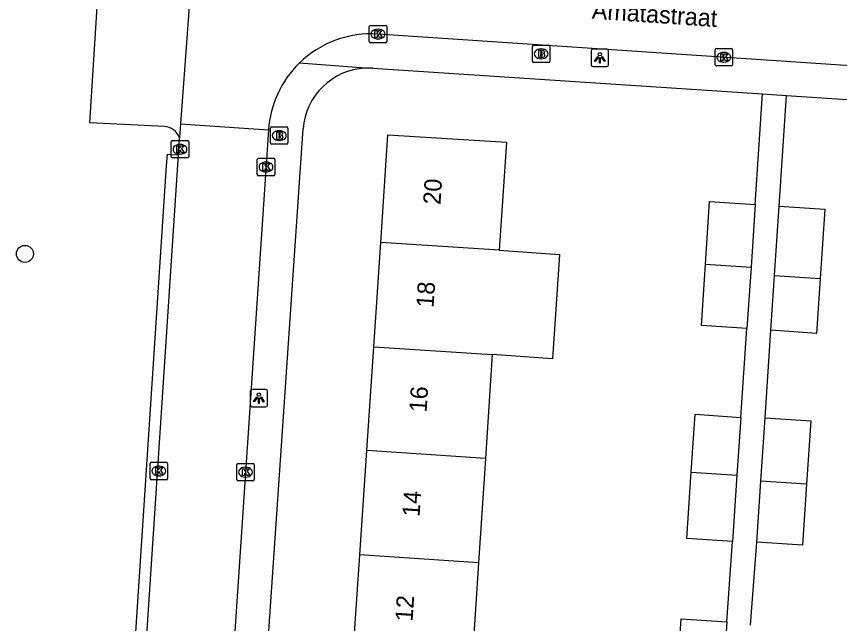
# Model space of a CAD drawing. Extents: x 161848 to 162726, y 385382 to 386521.
# Drawn here: x 161939.2 to 161986.5, y 385809.54 to 385844.42 of the extents above; entities that cross this region are included whole.
import ezdxf

# ---------------------------------------------------------------- set-up
doc = ezdxf.new("R2010")
doc.units = 0
for name, color, linetype in [('IMGEO_Boom', 7, 'Continuous'), ('IMGEO_Brandkraan', 7, 'Continuous'), ('IMGEO_Kolk', 7, 'Continuous'), ('IMGEO_Lichtpunt', 7, 'Continuous'), ('IMGEO_Openbare_ruimte_label', 7, 'Continuous'), ('IMGEO_Pand', 7, 'Continuous'), ('IMGEO_Pand_nummerreeks', 7, 'Continuous'), ('IMGEO_Parkeervlak_open', 7, 'Continuous'), ('IMGEO_Rijbaan_lokaal_open', 7, 'Continuous'), ('IMGEO_Verkeerseiland_open', 7, 'Continuous'), ('IMGEO_Voetpad_open', 7, 'Continuous')]:
    doc.layers.add(name, color=color, linetype=linetype)

msp = doc.modelspace()

# ---------------------------------------------------------------- linework, layer by layer
at = {"layer": 'IMGEO_Boom'}
msp.add_circle((161939.691, 385830.779), 0.489, dxfattribs=at)
at = {"layer": 'IMGEO_Brandkraan'}
for p, q in [((161968.848, 385841.847), (161968.848, 385842.699)), ((161968.923, 385842.773), (161969.775, 385842.773)), ((161969.336, 385842.553), (161969.361, 385842.553)), ((161969.849, 385842.699), (161969.849, 385841.847)), ((161969.359, 385841.993), (161969.334, 385841.993)), ((161969.775, 385841.773), (161968.923, 385841.773)), ((161953.803, 385837.151), (161953.803, 385838.003)), ((161953.878, 385838.077), (161954.73, 385838.077)), ((161954.291, 385837.857), (161954.316, 385837.857)), ((161954.804, 385838.003), (161954.804, 385837.151)), ((161954.314, 385837.297), (161954.289, 385837.297)), ((161954.73, 385837.077), (161953.878, 385837.077))]:
    msp.add_line(p, q, dxfattribs=at)
for points in [[(161968.848, 385841.847), (161968.848, 385842.699)], [(161968.923, 385842.773), (161969.775, 385842.773)], [(161969.196, 385842.473), (161969.196, 385842.073), (161969.409, 385842.073)], [(161969.427, 385842.473), (161969.196, 385842.473)], [(161969.375, 385842.392), (161969.321, 385842.392), (161969.321, 385842.316)], [(161969.849, 385842.699), (161969.849, 385841.847)], [(161969.321, 385842.316), (161969.374, 385842.316)], [(161969.383, 385842.24), (161969.321, 385842.24), (161969.321, 385842.159)], [(161969.321, 385842.159), (161969.383, 385842.159)], [(161969.775, 385841.773), (161968.923, 385841.773)], [(161953.803, 385837.151), (161953.803, 385838.003)], [(161953.878, 385838.077), (161954.73, 385838.077)], [(161954.151, 385837.777), (161954.151, 385837.377), (161954.364, 385837.377)], [(161954.382, 385837.777), (161954.151, 385837.777)], [(161954.33, 385837.696), (161954.276, 385837.696), (161954.276, 385837.62)], [(161954.804, 385838.003), (161954.804, 385837.151)], [(161954.276, 385837.62), (161954.329, 385837.62)], [(161954.338, 385837.544), (161954.276, 385837.544), (161954.276, 385837.463)], [(161954.276, 385837.463), (161954.338, 385837.463)], [(161954.73, 385837.077), (161953.878, 385837.077)]]:
    msp.add_lwpolyline(points, dxfattribs=at)
for centre, radius, start, end in [((161968.925, 385842.697), 0.0765, 91.552, 178.448), ((161968.925, 385842.697), 0.0765, 91.552, 178.448), ((161969.376, 385842.354), 0.0379, 267.8285, 90.9355), ((161969.431, 385842.328), 0.145, 59.4692, 91.5367), ((161969.456, 385842.375), 0.0922, 285.5137, 58.1501), ((161969.773, 385842.697), 0.0765, 1.552, 88.448), ((161969.773, 385842.697), 0.0765, 1.552, 88.448), ((161969.384, 385842.199), 0.0404, 269.8759, 90.5077), ((161969.415, 385842.324), 0.251, 268.6676, 293.5347), ((161969.461, 385842.183), 0.105, 301.3115, 78.989), ((161968.925, 385841.849), 0.0765, 181.552, 268.448), ((161968.925, 385841.849), 0.0765, 181.552, 268.448), ((161969.773, 385841.849), 0.0765, 271.552, 358.448), ((161969.773, 385841.849), 0.0765, 271.552, 358.448), ((161953.88, 385838.001), 0.0765, 91.552, 178.448), ((161953.88, 385838.001), 0.0765, 91.552, 178.448), ((161954.331, 385837.658), 0.0379, 267.8285, 90.9355), ((161954.386, 385837.632), 0.145, 59.4692, 91.5367), ((161954.411, 385837.679), 0.0922, 285.5137, 58.1501), ((161954.728, 385838.001), 0.0765, 1.552, 88.448), ((161954.728, 385838.001), 0.0765, 1.552, 88.448), ((161953.88, 385837.153), 0.0765, 181.552, 268.448), ((161953.88, 385837.153), 0.0765, 181.552, 268.448), ((161954.339, 385837.503), 0.0404, 269.8759, 90.5077), ((161954.37, 385837.628), 0.251, 268.6676, 293.5347), ((161954.416, 385837.487), 0.105, 301.3115, 78.989), ((161954.728, 385837.153), 0.0765, 271.552, 358.448), ((161954.728, 385837.153), 0.0765, 271.552, 358.448)]:
    msp.add_arc(centre, radius, start, end, dxfattribs=at)
for centre, major_axis, ratio, start_param, end_param in [((161969.335, 385842.273), (-0.387, 0.002), 0.722429, 4.712389, 7.853982), ((161969.36, 385842.273), (-0.39, 0.002), 0.717154, 1.570796, 4.712389), ((161954.29, 385837.577), (-0.387, 0.002), 0.722429, 4.712389, 7.853982), ((161954.315, 385837.577), (-0.39, 0.002), 0.717154, 1.570796, 4.712389)]:
    msp.add_ellipse(centre, major_axis=major_axis, ratio=ratio, start_param=start_param, end_param=end_param, dxfattribs=at)
at = {"layer": 'IMGEO_Kolk'}
for p, q in [((161959.477, 385842.983), (161959.477, 385843.835)), ((161959.552, 385843.909), (161960.404, 385843.909)), ((161960.478, 385843.835), (161960.478, 385842.983)), ((161959.965, 385843.689), (161959.99, 385843.689)), ((161960.404, 385842.909), (161959.552, 385842.909)), ((161959.988, 385843.129), (161959.963, 385843.129)), ((161979.346, 385841.649), (161979.346, 385842.501)), ((161979.421, 385842.575), (161980.273, 385842.575)), ((161979.834, 385842.355), (161979.859, 385842.355)), ((161980.347, 385842.501), (161980.347, 385841.649)), ((161980.273, 385841.575), (161979.421, 385841.575)), ((161979.857, 385841.795), (161979.832, 385841.795)), ((161948.098, 385836.363), (161948.098, 385837.215)), ((161948.173, 385837.289), (161949.025, 385837.289)), ((161949.099, 385837.215), (161949.099, 385836.363)), ((161948.586, 385837.069), (161948.611, 385837.069)), ((161949.025, 385836.289), (161948.173, 385836.289)), ((161948.609, 385836.509), (161948.584, 385836.509)), ((161953.116, 385836.269), (161953.968, 385836.269)), ((161953.041, 385835.343), (161953.041, 385836.195)), ((161953.529, 385836.049), (161953.554, 385836.049)), ((161954.042, 385836.195), (161954.042, 385835.343)), ((161953.968, 385835.269), (161953.116, 385835.269)), ((161953.552, 385835.489), (161953.527, 385835.489)), ((161946.886, 385817.876), (161946.886, 385818.728)), ((161946.961, 385818.802), (161947.813, 385818.802)), ((161947.887, 385818.728), (161947.887, 385817.876)), ((161951.937, 385818.737), (161952.789, 385818.737)), ((161947.374, 385818.582), (161947.399, 385818.582)), ((161951.862, 385817.811), (161951.862, 385818.663)), ((161952.35, 385818.517), (161952.375, 385818.517)), ((161952.863, 385818.663), (161952.863, 385817.811)), ((161947.813, 385817.802), (161946.961, 385817.802)), ((161947.397, 385818.022), (161947.372, 385818.022)), ((161952.373, 385817.957), (161952.348, 385817.957)), ((161952.789, 385817.737), (161951.937, 385817.737))]:
    msp.add_line(p, q, dxfattribs=at)
for points in [[(161959.477, 385842.983), (161959.477, 385843.835)], [(161959.552, 385843.909), (161960.404, 385843.909)], [(161960.478, 385843.835), (161960.478, 385842.983)], [(161959.798, 385843.609), (161959.921, 385843.609), (161959.921, 385843.458), (161960.051, 385843.609), (161960.215, 385843.609), (161960.069, 385843.458), (161960.222, 385843.209), (161960.07, 385843.209), (161959.985, 385843.373), (161959.921, 385843.306), (161959.921, 385843.209), (161959.798, 385843.209), (161959.798, 385843.609)], [(161960.404, 385842.909), (161959.552, 385842.909)], [(161979.346, 385841.649), (161979.346, 385842.501)], [(161979.421, 385842.575), (161980.273, 385842.575)], [(161980.347, 385842.501), (161980.347, 385841.649)], [(161979.667, 385842.275), (161979.79, 385842.275), (161979.79, 385842.124), (161979.92, 385842.275), (161980.084, 385842.275), (161979.938, 385842.124), (161980.091, 385841.875), (161979.939, 385841.875), (161979.854, 385842.039), (161979.79, 385841.972), (161979.79, 385841.875), (161979.667, 385841.875), (161979.667, 385842.275)], [(161980.273, 385841.575), (161979.421, 385841.575)], [(161948.098, 385836.363), (161948.098, 385837.215)], [(161948.173, 385837.289), (161949.025, 385837.289)], [(161949.099, 385837.215), (161949.099, 385836.363)], [(161948.419, 385836.989), (161948.542, 385836.989), (161948.542, 385836.838), (161948.672, 385836.989), (161948.836, 385836.989), (161948.69, 385836.838), (161948.843, 385836.589), (161948.691, 385836.589), (161948.606, 385836.753), (161948.542, 385836.686), (161948.542, 385836.589), (161948.419, 385836.589), (161948.419, 385836.989)], [(161949.025, 385836.289), (161948.173, 385836.289)], [(161953.116, 385836.269), (161953.968, 385836.269)], [(161953.041, 385835.343), (161953.041, 385836.195)], [(161953.362, 385835.969), (161953.485, 385835.969), (161953.485, 385835.818), (161953.615, 385835.969), (161953.779, 385835.969), (161953.633, 385835.818), (161953.786, 385835.569), (161953.634, 385835.569), (161953.549, 385835.733), (161953.485, 385835.666), (161953.485, 385835.569), (161953.362, 385835.569), (161953.362, 385835.969)], [(161954.042, 385836.195), (161954.042, 385835.343)], [(161953.968, 385835.269), (161953.116, 385835.269)], [(161946.886, 385817.876), (161946.886, 385818.728)], [(161946.961, 385818.802), (161947.813, 385818.802)], [(161947.887, 385818.728), (161947.887, 385817.876)], [(161951.937, 385818.737), (161952.789, 385818.737)], [(161947.207, 385818.502), (161947.33, 385818.502), (161947.33, 385818.351), (161947.46, 385818.502), (161947.624, 385818.502), (161947.478, 385818.351), (161947.631, 385818.102), (161947.479, 385818.102), (161947.394, 385818.266), (161947.33, 385818.199), (161947.33, 385818.102), (161947.207, 385818.102), (161947.207, 385818.502)], [(161951.862, 385817.811), (161951.862, 385818.663)], [(161952.183, 385818.437), (161952.306, 385818.437), (161952.306, 385818.286), (161952.436, 385818.437), (161952.6, 385818.437), (161952.454, 385818.286), (161952.607, 385818.037), (161952.455, 385818.037), (161952.37, 385818.201), (161952.306, 385818.134), (161952.306, 385818.037), (161952.183, 385818.037), (161952.183, 385818.437)], [(161952.863, 385818.663), (161952.863, 385817.811)], [(161947.813, 385817.802), (161946.961, 385817.802)], [(161952.789, 385817.737), (161951.937, 385817.737)]]:
    msp.add_lwpolyline(points, dxfattribs=at)
for centre, start, end in [((161959.554, 385843.833), 91.552, 178.448), ((161959.554, 385843.833), 91.552, 178.448), ((161960.402, 385843.833), 1.552, 88.448), ((161960.402, 385843.833), 1.552, 88.448), ((161959.554, 385842.985), 181.552, 268.448), ((161959.554, 385842.985), 181.552, 268.448), ((161960.402, 385842.985), 271.552, 358.448), ((161960.402, 385842.985), 271.552, 358.448), ((161979.423, 385842.499), 91.552, 178.448), ((161979.423, 385842.499), 91.552, 178.448), ((161980.271, 385842.499), 1.552, 88.448), ((161980.271, 385842.499), 1.552, 88.448), ((161979.423, 385841.651), 181.552, 268.448), ((161979.423, 385841.651), 181.552, 268.448), ((161980.271, 385841.651), 271.552, 358.448), ((161980.271, 385841.651), 271.552, 358.448), ((161948.175, 385837.213), 91.552, 178.448), ((161948.175, 385837.213), 91.552, 178.448), ((161949.023, 385837.213), 1.552, 88.448), ((161949.023, 385837.213), 1.552, 88.448), ((161948.175, 385836.365), 181.552, 268.448), ((161948.175, 385836.365), 181.552, 268.448), ((161949.023, 385836.365), 271.552, 358.448), ((161949.023, 385836.365), 271.552, 358.448), ((161953.118, 385836.193), 91.552, 178.448), ((161953.118, 385836.193), 91.552, 178.448), ((161953.966, 385836.193), 1.552, 88.448), ((161953.966, 385836.193), 1.552, 88.448), ((161953.118, 385835.345), 181.552, 268.448), ((161953.118, 385835.345), 181.552, 268.448), ((161953.966, 385835.345), 271.552, 358.448), ((161953.966, 385835.345), 271.552, 358.448), ((161946.963, 385818.726), 91.552, 178.448), ((161946.963, 385818.726), 91.552, 178.448), ((161947.811, 385818.726), 1.552, 88.448), ((161947.811, 385818.726), 1.552, 88.448), ((161951.939, 385818.661), 91.552, 178.448), ((161951.939, 385818.661), 91.552, 178.448), ((161952.787, 385818.661), 1.552, 88.448), ((161952.787, 385818.661), 1.552, 88.448), ((161946.963, 385817.878), 181.552, 268.448), ((161946.963, 385817.878), 181.552, 268.448), ((161947.811, 385817.878), 271.552, 358.448), ((161947.811, 385817.878), 271.552, 358.448), ((161951.939, 385817.813), 181.552, 268.448), ((161951.939, 385817.813), 181.552, 268.448), ((161952.787, 385817.813), 271.552, 358.448), ((161952.787, 385817.813), 271.552, 358.448)]:
    msp.add_arc(centre, 0.0765, start, end, dxfattribs=at)
for centre, major_axis, ratio, start_param, end_param in [((161959.964, 385843.409), (-0.387, 0.002), 0.722429, 4.712389, 7.853982), ((161959.989, 385843.409), (-0.39, 0.002), 0.717154, 1.570796, 4.712389), ((161979.833, 385842.075), (-0.387, 0.002), 0.722429, 4.712389, 7.853982), ((161979.858, 385842.075), (-0.39, 0.002), 0.717154, 1.570796, 4.712389), ((161948.585, 385836.789), (-0.387, 0.002), 0.722429, 4.712389, 7.853982), ((161948.61, 385836.789), (-0.39, 0.002), 0.717154, 1.570796, 4.712389), ((161953.528, 385835.769), (-0.387, 0.002), 0.722429, 4.712389, 7.853982), ((161953.553, 385835.769), (-0.39, 0.002), 0.717154, 1.570796, 4.712389), ((161947.373, 385818.302), (-0.387, 0.002), 0.722429, 4.712389, 7.853982), ((161947.398, 385818.302), (-0.39, 0.002), 0.717154, 1.570796, 4.712389), ((161952.349, 385818.237), (-0.387, 0.002), 0.722429, 4.712389, 7.853982), ((161952.374, 385818.237), (-0.39, 0.002), 0.717154, 1.570796, 4.712389)]:
    msp.add_ellipse(centre, major_axis=major_axis, ratio=ratio, start_param=start_param, end_param=end_param, dxfattribs=at)
at = {"layer": 'IMGEO_Lichtpunt'}
for p, q in [((161972.227, 385842.451), (161972.227, 385841.644)), ((161972.227, 385842.451), (161972.227, 385841.644)), ((161973.129, 385842.546), (161972.321, 385842.546)), ((161973.129, 385842.546), (161972.321, 385842.546)), ((161973.223, 385841.644), (161973.223, 385842.451)), ((161973.223, 385841.644), (161973.223, 385842.451)), ((161972.321, 385841.55), (161973.129, 385841.55)), ((161972.321, 385841.55), (161973.129, 385841.55)), ((161953.535, 385822.99), (161952.727, 385822.99)), ((161953.535, 385822.99), (161952.727, 385822.99)), ((161952.633, 385822.895), (161952.633, 385822.088)), ((161952.633, 385822.895), (161952.633, 385822.088)), ((161953.629, 385822.088), (161953.629, 385822.895)), ((161953.629, 385822.088), (161953.629, 385822.895)), ((161952.727, 385821.994), (161953.535, 385821.994)), ((161952.727, 385821.994), (161953.535, 385821.994))]:
    msp.add_line(p, q, dxfattribs=at)
for points in [[(161972.601, 385842.115), (161972.64, 385842.087), (161972.452, 385841.825), (161972.414, 385841.852), (161972.601, 385842.115)], [(161972.703, 385842.067), (161972.75, 385842.067), (161972.75, 385841.745), (161972.703, 385841.745), (161972.703, 385842.067)], [(161972.813, 385842.087), (161972.851, 385842.114), (161973.038, 385841.852), (161972.999, 385841.824), (161972.813, 385842.087)], [(161953.007, 385822.559), (161953.046, 385822.531), (161952.858, 385822.269), (161952.82, 385822.296), (161953.007, 385822.559)], [(161953.109, 385822.511), (161953.156, 385822.511), (161953.156, 385822.189), (161953.109, 385822.189), (161953.109, 385822.511)], [(161953.219, 385822.531), (161953.257, 385822.558), (161953.444, 385822.296), (161953.405, 385822.268), (161953.219, 385822.531)]]:
    msp.add_lwpolyline(points, dxfattribs=at)
for centre in [(161972.726, 385842.249), (161953.132, 385822.693)]:
    msp.add_circle(centre, 0.0994, dxfattribs=at)
for centre, start, end in [((161972.321, 385842.451), 90, 180), ((161972.321, 385842.451), 90, 180), ((161973.129, 385842.451), 0, 90), ((161973.129, 385842.451), 0, 90), ((161972.321, 385841.644), 180, 270), ((161972.321, 385841.644), 180, 270), ((161973.129, 385841.644), 270, 0), ((161973.129, 385841.644), 270, 360), ((161952.727, 385822.895), 90, 180), ((161952.727, 385822.895), 90, 180), ((161953.535, 385822.895), 0, 90), ((161953.535, 385822.895), 0, 90), ((161952.727, 385822.088), 180, 270), ((161952.727, 385822.088), 180, 270), ((161953.535, 385822.088), 270, 0), ((161953.535, 385822.088), 270, 360)]:
    msp.add_arc(centre, 0.0946, start, end, dxfattribs=at)
at = {"layer": 'IMGEO_Pand'}
for points in [[(161960.132, 385831.44), (161960.546, 385837.627), (161967.351, 385837.188), (161966.94, 385830.984)], [(161978.792, 385830.19), (161979.031, 385833.792), (161981.653, 385833.619)], [(161981.653, 385833.619), (161981.414, 385830.015)], [(161982.767, 385829.543), (161983.031, 385833.522)], [(161983.031, 385833.522), (161985.651, 385833.348), (161985.387, 385829.37)], [(161959.731, 385825.445), (161960.132, 385831.44)], [(161966.94, 385830.984), (161960.132, 385831.44)], [(161966.94, 385830.984), (161970.408, 385830.752), (161970.006, 385824.757), (161966.543, 385824.989)], [(161981.18, 385826.49), (161978.559, 385826.664), (161978.792, 385830.19)], [(161978.792, 385830.19), (161981.414, 385830.015)], [(161981.414, 385830.015), (161981.18, 385826.49)], [(161982.558, 385826.386), (161982.767, 385829.543)], [(161985.387, 385829.37), (161985.178, 385826.212), (161982.558, 385826.386)], [(161982.767, 385829.543), (161985.387, 385829.37)], [(161959.331, 385819.481), (161959.731, 385825.445)], [(161959.731, 385825.445), (161966.543, 385824.989)], [(161966.543, 385824.989), (161966.148, 385819.025)], [(161977.978, 385818.234), (161978.199, 385821.56), (161980.821, 385821.387)], [(161980.821, 385821.387), (161980.6, 385818.058)], [(161981.979, 385817.712), (161982.22, 385821.354)], [(161982.22, 385821.354), (161984.84, 385821.18), (161984.599, 385817.539)], [(161958.93, 385813.487), (161959.331, 385819.481)], [(161966.148, 385819.025), (161959.331, 385819.481)], [(161966.148, 385819.025), (161965.751, 385813.03)], [(161980.348, 385814.258), (161977.727, 385814.432), (161977.978, 385818.234)], [(161977.978, 385818.234), (161980.6, 385818.058)], [(161980.6, 385818.058), (161980.348, 385814.258)], [(161981.747, 385814.218), (161981.979, 385817.712)], [(161984.599, 385817.539), (161984.367, 385814.044), (161981.747, 385814.218)], [(161984.599, 385817.539), (161981.979, 385817.712)], [(161958.535, 385807.578), (161958.93, 385813.487)], [(161965.751, 385813.03), (161958.93, 385813.487)], [(161965.751, 385813.03), (161965.359, 385807.121)], [(161977.162, 385806.331), (161977.392, 385809.804), (161980.014, 385809.631)], [(161980.014, 385809.631), (161979.783, 385806.155)]]:
    msp.add_lwpolyline(points, dxfattribs=at)
at = {"layer": 'IMGEO_Parkeervlak_open'}
msp.add_lwpolyline([(161947.7, 385838.093), (161943.41, 385838.314), (161943.973, 385847.108)], dxfattribs=at)
msp.add_arc((161947.651, 385837.125), 0.969, 19.1981, 87.1044, dxfattribs=at)
at = {"layer": 'IMGEO_Rijbaan_lokaal_open'}
for points in [[(161949.439, 385849.157), (161948.626, 385838.255)], [(162011.852, 385839.801), (162006.813, 385840.179), (162000, 385840.722), (161959.982, 385843.41)], [(161948.626, 385838.255), (161948.566, 385837.444)], [(161948.626, 385838.255), (161953.684, 385837.905)], [(161953.684, 385837.905), (161951.056, 385798.814), (161949.827, 385779.824)], [(161948.494, 385836.471), (161948.566, 385837.444)], [(161948.494, 385836.471), (161944.769, 385780.141)]]:
    msp.add_lwpolyline(points, dxfattribs=at)
for centre, radius, start, end in [((161959.593, 385837.49), 5.933, 86.2376, 134.398), ((161959.597, 385837.503), 5.927, 134.5137, 176.1072)]:
    msp.add_arc(centre, radius, start, end, dxfattribs=at)
at = {"layer": 'IMGEO_Verkeerseiland_open'}
msp.add_lwpolyline([(161943.443, 385768.793), (161945.684, 385803.221), (161947.829, 385835.828), (161947.874, 385836.512), (161948.121, 385836.496), (161948.494, 385836.471)], dxfattribs=at)
at = {"layer": 'IMGEO_Voetpad_open'}
for points in [[(161959.249, 385841.452), (161955.442, 385841.729)], [(161959.679, 385841.448), (161982.073, 385839.965)], [(161981.653, 385833.619), (161982.073, 385839.965)], [(161982.073, 385839.965), (161983.452, 385839.874)], [(161983.031, 385833.522), (161983.452, 385839.874)], [(161983.452, 385839.874), (162000, 385838.778), (162007.405, 385838.156), (162010.612, 385837.904)], [(161951.696, 385779.71), (161955.683, 385837.954)], [(161980.821, 385821.387), (161981.18, 385826.49)], [(161982.22, 385821.354), (161982.558, 385826.386)], [(161980.014, 385809.631), (161980.348, 385814.258)], [(161981.378, 385809.448), (161981.747, 385814.218)]]:
    msp.add_lwpolyline(points, dxfattribs=at)
for centre, radius, start, end in [((161959.43, 385837.701), 3.756, 92.7645, 176.1324), ((161959.428, 385837.601), 3.856, 86.2702, 92.6638)]:
    msp.add_arc(centre, radius, start, end, dxfattribs=at)

# ---------------------------------------------------------------- texts
at = {"layer": 'IMGEO_Openbare_ruimte_label'}
msp.add_text('Amatastraat', height=1, rotation=356.1593, dxfattribs=at).set_placement((161972.244, 385844.294))
at = {"layer": 'IMGEO_Pand_nummerreeks'}
for s, rotation, p in [('20', 86.1705, (161963.562, 385833.583)), ('18', 86.1729, (161963.166, 385827.667)), ('16', 86.1705, (161962.764, 385821.656)), ('14', 86.1705, (161962.362, 385815.649)), ('12', 86.1705, (161961.96, 385809.639))]:
    msp.add_text(s, height=1, rotation=rotation, dxfattribs=at).set_placement(p)

doc.saveas('drawing.dxf')
